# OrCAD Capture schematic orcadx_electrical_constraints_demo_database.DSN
size B
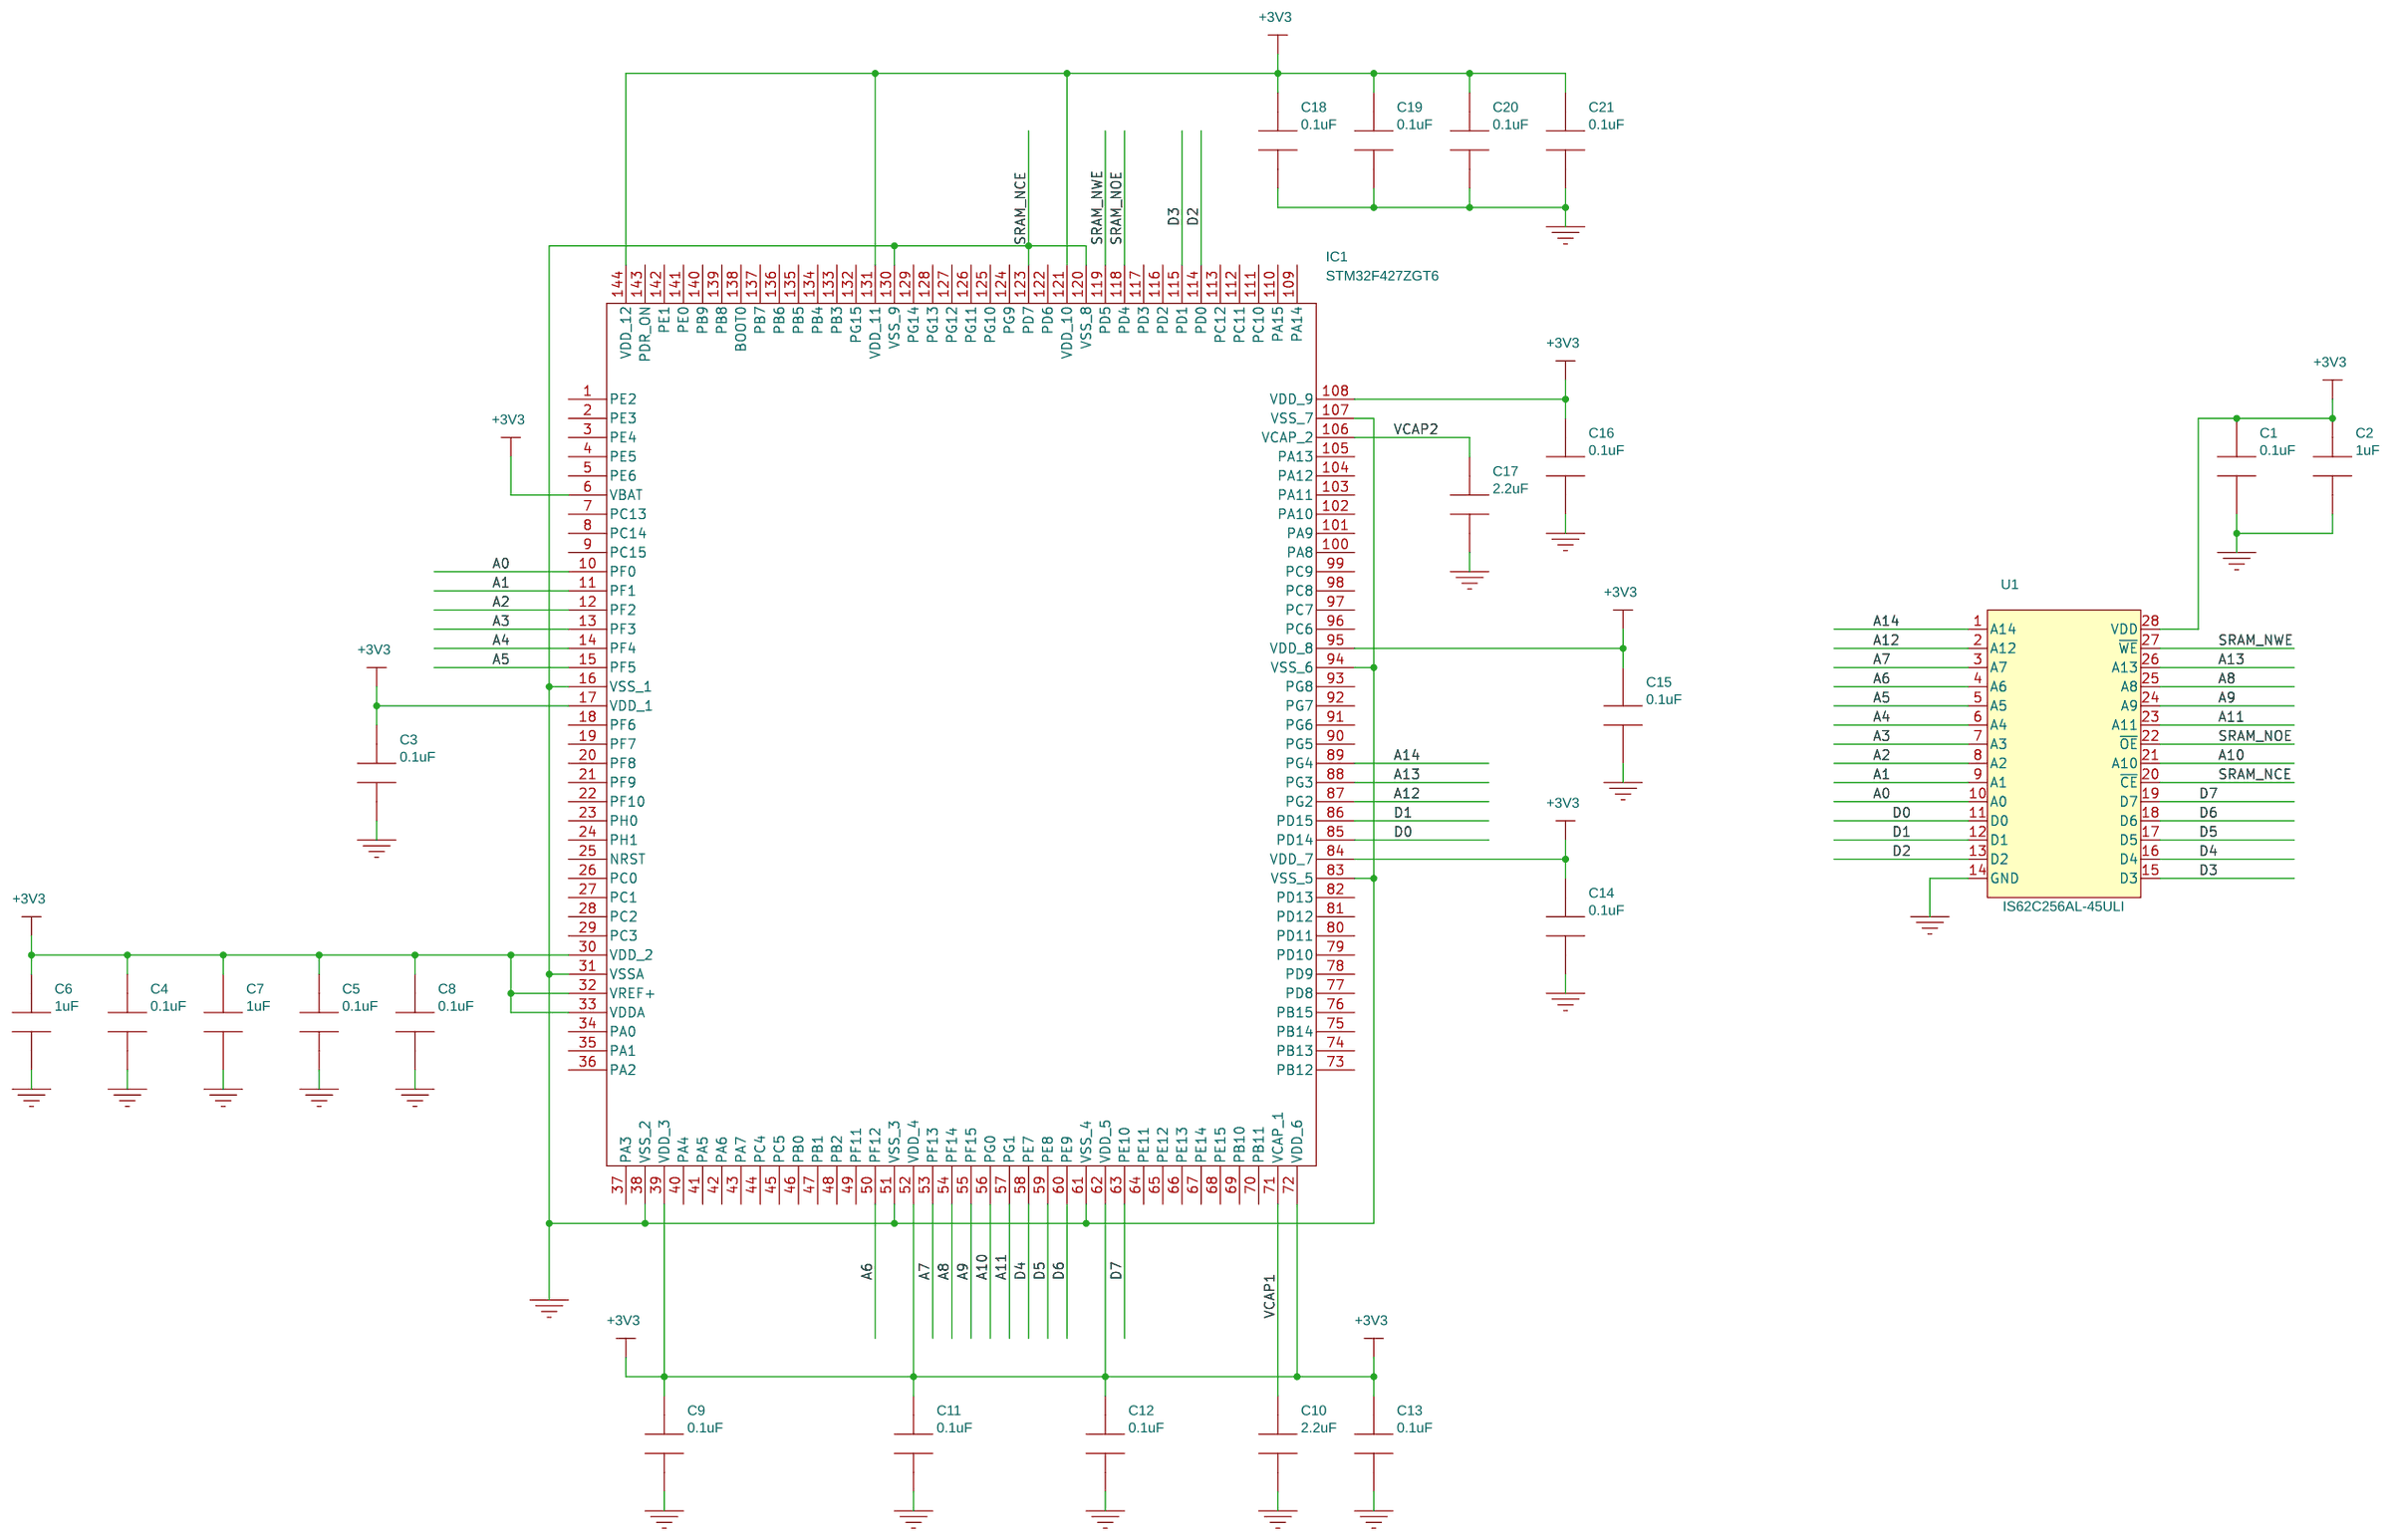
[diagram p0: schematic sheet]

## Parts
C1  0.1uF  [cap0603]
C2  1uF  [cap0603]
C3  0.1uF  [cap0603]
C4  0.1uF  [cap0603]
C5  0.1uF  [cap0603]
C6  1uF  [cap0603]
C7  1uF  [cap0603]
C8  0.1uF  [cap0603]
C9  0.1uF  [cap0603]
C10  2.2uF  [cap0603]
C11  0.1uF  [cap0603]
C12  0.1uF  [cap0603]
C13  0.1uF  [cap0603]
C14  0.1uF  [cap0603]
C15  0.1uF  [cap0603]
C16  0.1uF  [cap0603]
C17  2.2uF  [cap0603]
C18  0.1uF  [cap0603]
C19  0.1uF  [cap0603]
C20  0.1uF  [cap0603]
C21  0.1uF  [cap0603]
IC1  STM32F427ZGT6  [QFP50P2200X2200X160-144N]
U1  IS62C256AL-45ULI  [28-SOP]

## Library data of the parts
C1 C3-C5 C8 C9 C11-C16 C18-C21 = CAP1: PACKAGE: 0603; Part Number: CDN-CAP-0001; TC: X7R; VOLTAGE: 50V; cdn_wsid: local
C2 C6 C7 = CAP1: PACKAGE: 0603; Part Number: CDN-CAP-0002; TC: X5R; VOLTAGE: 25V; cdn_wsid: local
C10 C17 = CAP1: PACKAGE: 0603; Part Number: CDN-CAP-0003; TC: X5R; VOLTAGE: 16V; cdn_wsid: local
IC1 = STM32F427ZGT6: Manufacturer Name: STMicroelectronics
U1 = IS62C256AL-45ULI: GENERIC_NAME: IS62C256AL; Part Number: CDN-IC-0005; VOLTAGE_SUPPLY: 2.4V-5V; cdn_wsid: local

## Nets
+3V3: C1.1 C2.1 C3.1 C4.1 C5.1 C6.1 C7.1 C8.1 C9.1 C11.1 C12.1 C13.1 C14.1 C15.1 C16.1 C18.1 C19.1 C20.1 C21.1 IC1.6(VBAT) IC1.17(VDD_1) IC1.30(VDD_2) IC1.32(VREF+) IC1.33(VDDA) IC1.39(VDD_3) IC1.52(VDD_4) IC1.62(VDD_5) IC1.72(VDD_6) IC1.84(VDD_7) IC1.95(VDD_8) IC1.108(VDD_9) IC1.121(VDD_10) IC1.131(VDD_11) IC1.144(VDD_12) U1.28(VDD)
GND: C1.2 C2.2 C3.2 C4.2 C5.2 C6.2 C7.2 C8.2 C9.2 C10.2 C11.2 C12.2 C13.2 C14.2 C15.2 C16.2 C17.2 C18.2 C19.2 C20.2 C21.2 IC1.16(VSS_1) IC1.31(VSSA) IC1.38(VSS_2) IC1.51(VSS_3) IC1.61(VSS_4) IC1.83(VSS_5) IC1.94(VSS_6) IC1.107(VSS_7) IC1.120(VSS_8) IC1.130(VSS_9) U1.14(GND)
A0: IC1.10(PF0) U1.10(A0)
A1: IC1.11(PF1) U1.9(A1)
A2: IC1.12(PF2) U1.8(A2)
A3: IC1.13(PF3) U1.7(A3)
A4: IC1.14(PF4) U1.6(A4)
A5: IC1.15(PF5) U1.5(A5)
A6: IC1.50(PF12) U1.4(A6)
A7: IC1.53(PF13) U1.3(A7)
A8: IC1.54(PF14) U1.25(A8)
A9: IC1.55(PF15) U1.24(A9)
A10: IC1.56(PG0) U1.21(A10)
A11: IC1.57(PG1) U1.23(A11)
A12: IC1.87(PG2) U1.2(A12)
A13: IC1.88(PG3) U1.26(A13)
A14: IC1.89(PG4) U1.1(A14)
D0: IC1.85(PD14) U1.11(D0)
D1: IC1.86(PD15) U1.12(D1)
D2: IC1.114(PD0) U1.13(D2)
D3: IC1.115(PD1) U1.15(D3)
D4: IC1.58(PE7) U1.16(D4)
D5: IC1.59(PE8) U1.17(D5)
D6: IC1.60(PE9) U1.18(D6)
D7: IC1.63(PE10) U1.19(D7)
SRAM_NCE: IC1.123(PD7) U1.20(~{CE})
SRAM_NOE: IC1.118(PD4) U1.22(~{OE})
SRAM_NWE: IC1.119(PD5) U1.27(~{WE})
VCAP1: C10.1 IC1.71(VCAP_1)
VCAP2: C17.1 IC1.106(VCAP_2)

Not connected (* = marked no-connect by the designer): IC1 1(PE2) 2(PE3) 3(PE4) 4(PE5) 5(PE6) 7(PC13) 8(PC14) 9(PC15) 18(PF6) 19(PF7) 20(PF8) 21(PF9) 22(PF10) 23(PH0) 24(PH1) 25(NRST) 26(PC0) 27(PC1) 28(PC2) 29(PC3) 34(PA0) 35(PA1) 36(PA2) 37(PA3) 40(PA4) 41(PA5) 42(PA6) 43(PA7) 44(PC4) 45(PC5) 46(PB0) 47(PB1) 48(PB2) 49(PF11) 64(PE11) 65(PE12) 66(PE13) 67(PE14) 68(PE15) 69(PB10) 70(PB11) 73(PB12) 74(PB13) 75(PB14) 76(PB15) 77(PD8) 78(PD9) 79(PD10) 80(PD11) 81(PD12) 82(PD13) 90(PG5) 91(PG6) 92(PG7) 93(PG8) 96(PC6) 97(PC7) 98(PC8) 99(PC9) 100(PA8) 101(PA9) 102(PA10) 103(PA11) 104(PA12) 105(PA13) 109(PA14) 110(PA15) 111(PC10) 112(PC11) 113(PC12) 116(PD2) 117(PD3) 122(PD6) 124(PG9) 125(PG10) 126(PG11) 127(PG12) 128(PG13) 129(PG14) 132(PG15) 133(PB3) 134(PB4) 135(PB5) 136(PB6) 137(PB7) 138(BOOT0) 139(PB8) 140(PB9) 141(PE0) 142(PE1) 143(PDR_ON)
